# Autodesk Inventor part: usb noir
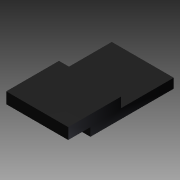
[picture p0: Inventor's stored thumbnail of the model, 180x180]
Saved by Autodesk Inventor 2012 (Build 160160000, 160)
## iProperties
Created: 2013-04
Part Number: usb noir
Material: Default
Document SubType Name: Modeling
Designer: hilarion
Density: 1 g/cm^3
Author: hilarion
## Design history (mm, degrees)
sketch "Esquisse1"
  geometry: L1 (0, 0)-(11.16, 0); L2 (11.16, 0)-(11.16, 19); L3 (11.16, 19)-(0, 19); L4 (0, 19)-(0, 0)
  constraints: 8 end point, 2 parallel, 1 horizontal, 1 perpendicular
  dimensions: "d0" = 19 distance between parallel lines of L1 L3; "d1" = 11.16 distance between parallel lines of L2 L4
extrude "Extrusion1" new body sketch "Esquisse1" distance "d2" = 3.5; taper "d3" = 0 deg
sketch "Esquisse2"
  geometry: L1 (-3.5, 19)-(-3.5, 0) reference; L2 (-3.5, 19)-(-1.7, 19); L3 (-1.7, 19)-(-1.7, 9.5); L4 (-1.7, 9.5)-(-3.5, 9.5); L5 (-3.5, 9.5)-(-3.5, 19)
  constraints: 8 end point, 2 parallel, 1 horizontal, 1 perpendicular
  dimensions: "d4" = 9.5 distance between parallel lines of L4 L2; "d5" = 1.8 distance between parallel lines of L3 L1
extrude "Extrusion2" cut sketch "Esquisse2" stored distance "d6" = 3.5; taper "d7" = 0 deg
sketch "Esquisse3"
  geometry: L1 (-3.5, 9.5)-(-3.5, 0) reference; L2 (0, 19)-(-1.7, 19) reference; L3 (0, 0)-(-0.9, 0); L4 (-0.9, 0)-(-0.9, 4); L5 (-0.9, 4)-(0, 4); L6 (0, 4)-(0, 0)
  constraints: 8 end point, 2 parallel, 1 horizontal, 1 perpendicular
  dimensions: "d8" = 15 distance between parallel lines of L5 L2; "d9" = 2.6 distance between parallel lines of L1 L4
extrude "Extrusion3" cut sketch "Esquisse3" stored distance "d10" = 3.5; taper "d11" = 0 deg
sketch "Esquisse4"
  geometry: L1 (-2.6, 4)-(-2.6, 0) reference; L2 (-2.6, 0)-(0, 0) reference; L3 (0, 0)-(0, 9.5) reference; L4 (-2.6, 4)-(-2, 4); L5 (-2, 4)-(-2, 0); L6 (-2, 0)-(-2.6, 0); L7 (-2.6, 0)-(-2.6, 4); 1 further point
  constraints: 8 end point, 2 parallel, 1 horizontal, 1 perpendicular, 1 point on line
  dimensions: "d12" = 2 distance between parallel lines of L3 L5
extrude "Extrusion4" cut sketch "Esquisse4" stored distance "d13" = 10; taper "d14" = 0 deg
node "Solide1"
